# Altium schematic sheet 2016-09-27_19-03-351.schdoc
size 513 x 205 mm; SheetNumber: 1; SheetTotal: 1
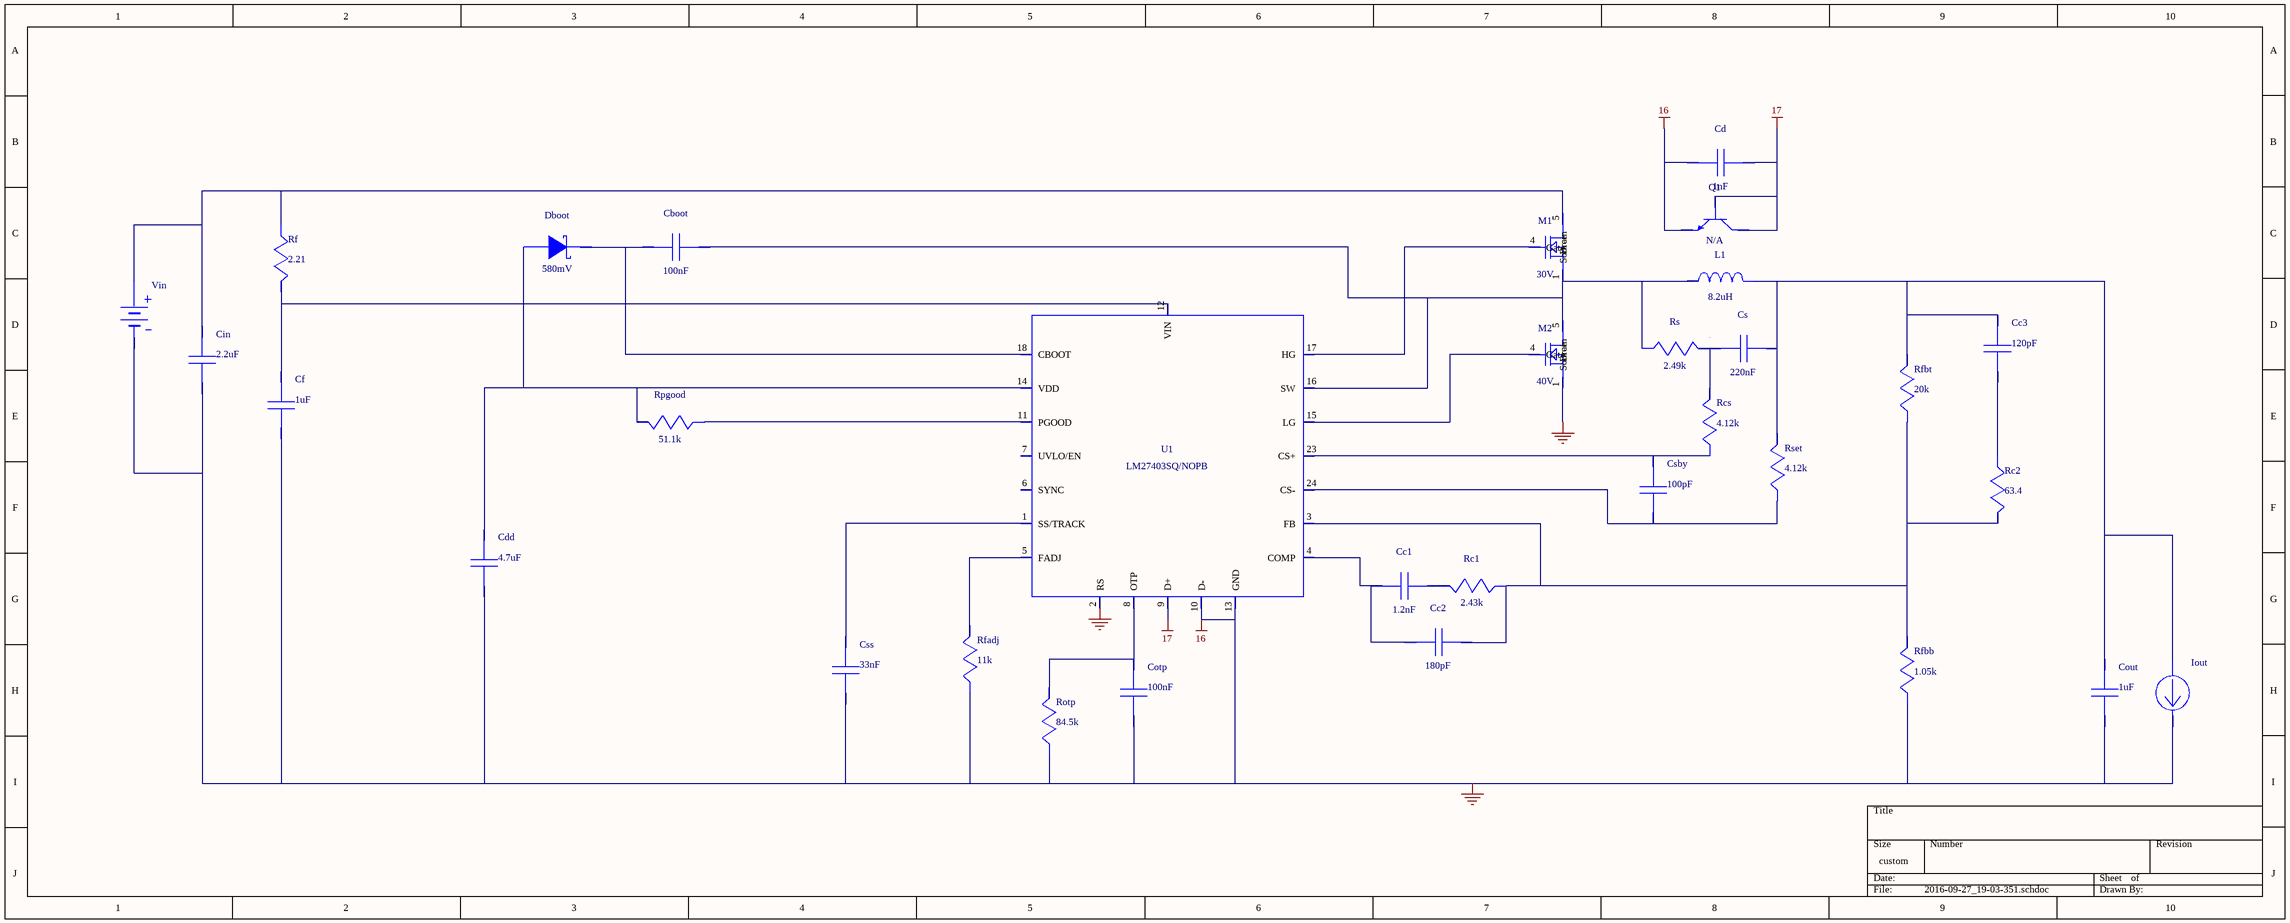
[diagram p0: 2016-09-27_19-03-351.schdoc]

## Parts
Cboot  value 100nF  (hidden comment: GRM155R61C104KA88D)
Cc1  value 1.2nF  (hidden comment: CL21C122JBFNNWE)
Cc2  value 180pF  (hidden comment: C0805C181K5GACTU)
Cc3  value 120pF  (hidden comment: CL21C121JB61PNC)
Cd  value 1nF  (hidden comment: GRM033R71C102KA01D)
Cdd  value 4.7uF  (hidden comment: LMK212BJ475KD-T)
Cf  value 1uF  (hidden comment: GRM188R61E105KA12D)
Cin  value 2.2uF  (hidden comment: GRM21BR61E225KA12L)
Cotp  value 100nF  (hidden comment: GRM155R61A104KA01D)
Cout  value 1uF  (hidden comment: GRM188R61C105KA93D)
Cs  value 220nF  (hidden comment: GRM155R71C224KA12D)
Csby  value 100pF  (hidden comment: 08055A101JAT2A)
Css  value 33nF  (hidden comment: GRM033R60J333KE01D)
Dboot  value 580mV  (hidden comment: SBR0230T5-7-F)
Iout  WB_CURRENT_LOAD  (value not drawn)
L1  value 8.2uH  (hidden comment: SRU1048-8R2Y)
M1  value 30V  (hidden comment: CSD17308Q3)
M2  value 40V  (hidden comment: CSD18504Q5A)
Q1  MMBT3904T  (value not drawn)
Rc1  value 2.43k  (hidden comment: CRCW04022K43FKED)
Rc2  value 63.4  (hidden comment: CRCW040263R4FKED)
Rcs  value 4.12k  (hidden comment: CRCW04024K12FKED)
Rf  value 2.21  (hidden comment: CRCW04022R21FKED)
Rfadj  value 11k  (hidden comment: CRCW040211K0FKED)
Rfbb  value 1.05k  (hidden comment: CRCW04021K05FKED)
Rfbt  value 20k  (hidden comment: CRCW040220K0FKED)
Rotp  value 84.5k  (hidden comment: CRCW040284K5FKED)
Rpgood  value 51.1k  (hidden comment: CRCW040251K1FKED)
Rs  value 2.49k  (hidden comment: CRCW04022K49FKED)
Rset  value 4.12k  (hidden comment: CRCW04024K12FKED)
U1  LM27403SQ/NOPB
Vin  WB_BATTERY  (value not drawn)

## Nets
0: Cd.2 Cdd.2 Cf.1 Cin.2 Cotp.2 Cout.2 Css.2 Iout.2(-) M2.1(Source) M2.2(Source) M2.3(Source) Q1.2(Emitter) Rfadj.2 Rfbb.2 Rotp.2 U1.2(RS) U1.10(D-) U1.13(GND) U1.19(NC) U1.20(NC) U1.21(NC) U1.22(NC) U1.25(EP) Vin.2(-)  [also labelled 16]
17: Cd.1 Q1.1(Base) Q1.3(Collector) U1.9(D+)
NetCboot_1: Cboot.1 L1.1 M1.1(Source) M1.2(Source) M1.3(Source) M2.5(Drain) M2.6(Drain) M2.7(Drain) M2.8(Drain) M2.9(Drain) Rs.2 U1.16(SW)
NetCboot_2: Cboot.2 Dboot.1(K) U1.18(CBOOT)
NetCc1_1: Cc1.1 Rc1.1
NetCc1_2: Cc1.2 Cc2.1 U1.4(COMP)
NetCc2_2: Cc2.2 Rc1.2 Rc2.1 Rfbb.1 Rfbt.2 U1.3(FB)
NetCc3_1: Cc3.1 Cout.1 Cs.2 Iout.1(+) L1.2 Rfbt.1 Rset.1
NetCc3_2: Cc3.2 Rc2.2
NetCdd_1: Cdd.1 Dboot.2(A) Rpgood.1 U1.14(VDD)
NetCf_2: Cf.2 Rf.1 U1.12(VIN)
NetCin_1: Cin.1 M1.5(Drain) M1.6(Drain) M1.7(Drain) M1.8(Drain) M1.9(Drain) Rf.2 Vin.1(+)
NetCotp_1: Cotp.1 Rotp.1 U1.8(OTP)
NetCs_1: Cs.1 Rcs.1 Rs.1
NetCsby_1: Csby.1 Rset.2 U1.24(CS-)
NetCsby_2: Csby.2 Rcs.2 U1.23(CS+)
NetCss_1: Css.1 U1.1(SS/TRACK)
NetM1_4: M1.4(Gate) U1.17(HG)
NetM2_4: M2.4(Gate) U1.15(LG)
NetRfadj_1: Rfadj.1 U1.5(FADJ)
NetRpgood_2: Rpgood.2 U1.11(PGOOD)

Not connected (* = marked no-connect by the designer): U1 6(SYNC) 7(UVLO/EN)

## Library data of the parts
Cboot = GRM155R61C104KA88D: GRM155R61C104KA8; Manufacturer Name: MuRata
Cc1 = CL21C122JBFNNWE: Manufacturer Name: Samsung Electro-Mechanics
Cc2 = C0805C181K5GACTU: Manufacturer Name: Kemet
Cc3 = CL21C121JB61PNC: Manufacturer Name: Samsung Electro-Mechanics
Cd = GRM033R71C102KA01D: GRM033R71C102KA0; Manufacturer Name: MuRata
Cdd = LMK212BJ475KD-T: Manufacturer Name: Taiyo Yuden
Cf = GRM188R61E105KA12D: GRM188R61E105KA1; Manufacturer Name: MuRata
Cin = GRM21BR61E225KA12L: GRM21BR61E225KA1; Manufacturer Name: MuRata
Cotp = GRM155R61A104KA01D: GRM155R61A104KA0; Manufacturer Name: MuRata
Cout = GRM188R61C105KA93D: GRM188R61C105KA9; Manufacturer Name: MuRata
Cs = GRM155R71C224KA12D: GRM155R71C224KA1; Manufacturer Name: MuRata
Csby = 08055A101JAT2A: Manufacturer Name: AVX
Css = GRM033R60J333KE01D: GRM033R60J333KE0; Manufacturer Name: MuRata
Dboot = SBR0230T5-7-F: Manufacturer Name: Diodes Inc.
L1 = SRU1048-8R2Y: Manufacturer Name: Bourns
M1 = CSD17308Q3: Manufacturer Name: Texas Instruments
M2 = CSD18504Q5A: Manufacturer Name: Texas Instruments
Q1 = MMBT3904T: Manufacturer Name: Diodes Inc.
Rc1 = CRCW04022K43FKED: Manufacturer Name: Vishay-Dale
Rc2 = CRCW040263R4FKED: Manufacturer Name: Vishay-Dale
Rcs Rset = CRCW04024K12FKED: Manufacturer Name: Vishay-Dale
Rf = CRCW04022R21FKED: Manufacturer Name: Vishay-Dale
Rfadj = CRCW040211K0FKED: Manufacturer Name: Vishay-Dale
Rfbb = CRCW04021K05FKED: Manufacturer Name: Vishay-Dale
Rfbt = CRCW040220K0FKED: Manufacturer Name: Vishay-Dale
Rotp = CRCW040284K5FKED: Manufacturer Name: Vishay-Dale
Rpgood = CRCW040251K1FKED: Manufacturer Name: Vishay-Dale
Rs = CRCW04022K49FKED: Manufacturer Name: Vishay-Dale
U1 = LM27403SQ/NOPB: Manufacturer Name: Texas Instruments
